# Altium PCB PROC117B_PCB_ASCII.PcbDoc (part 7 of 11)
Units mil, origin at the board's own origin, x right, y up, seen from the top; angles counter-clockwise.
Board outline 2480.32 x 3185.25 mil, 8 copper layers (Top Layer, L2_GND1, L3_SIG1, L4_PWR1, L5_PWR2, L6_SIG2, L7_GND2, Bottom Layer), stack 57.4 mil thick; 456 components, 292 nets, 7831 pads, 2905 vias.
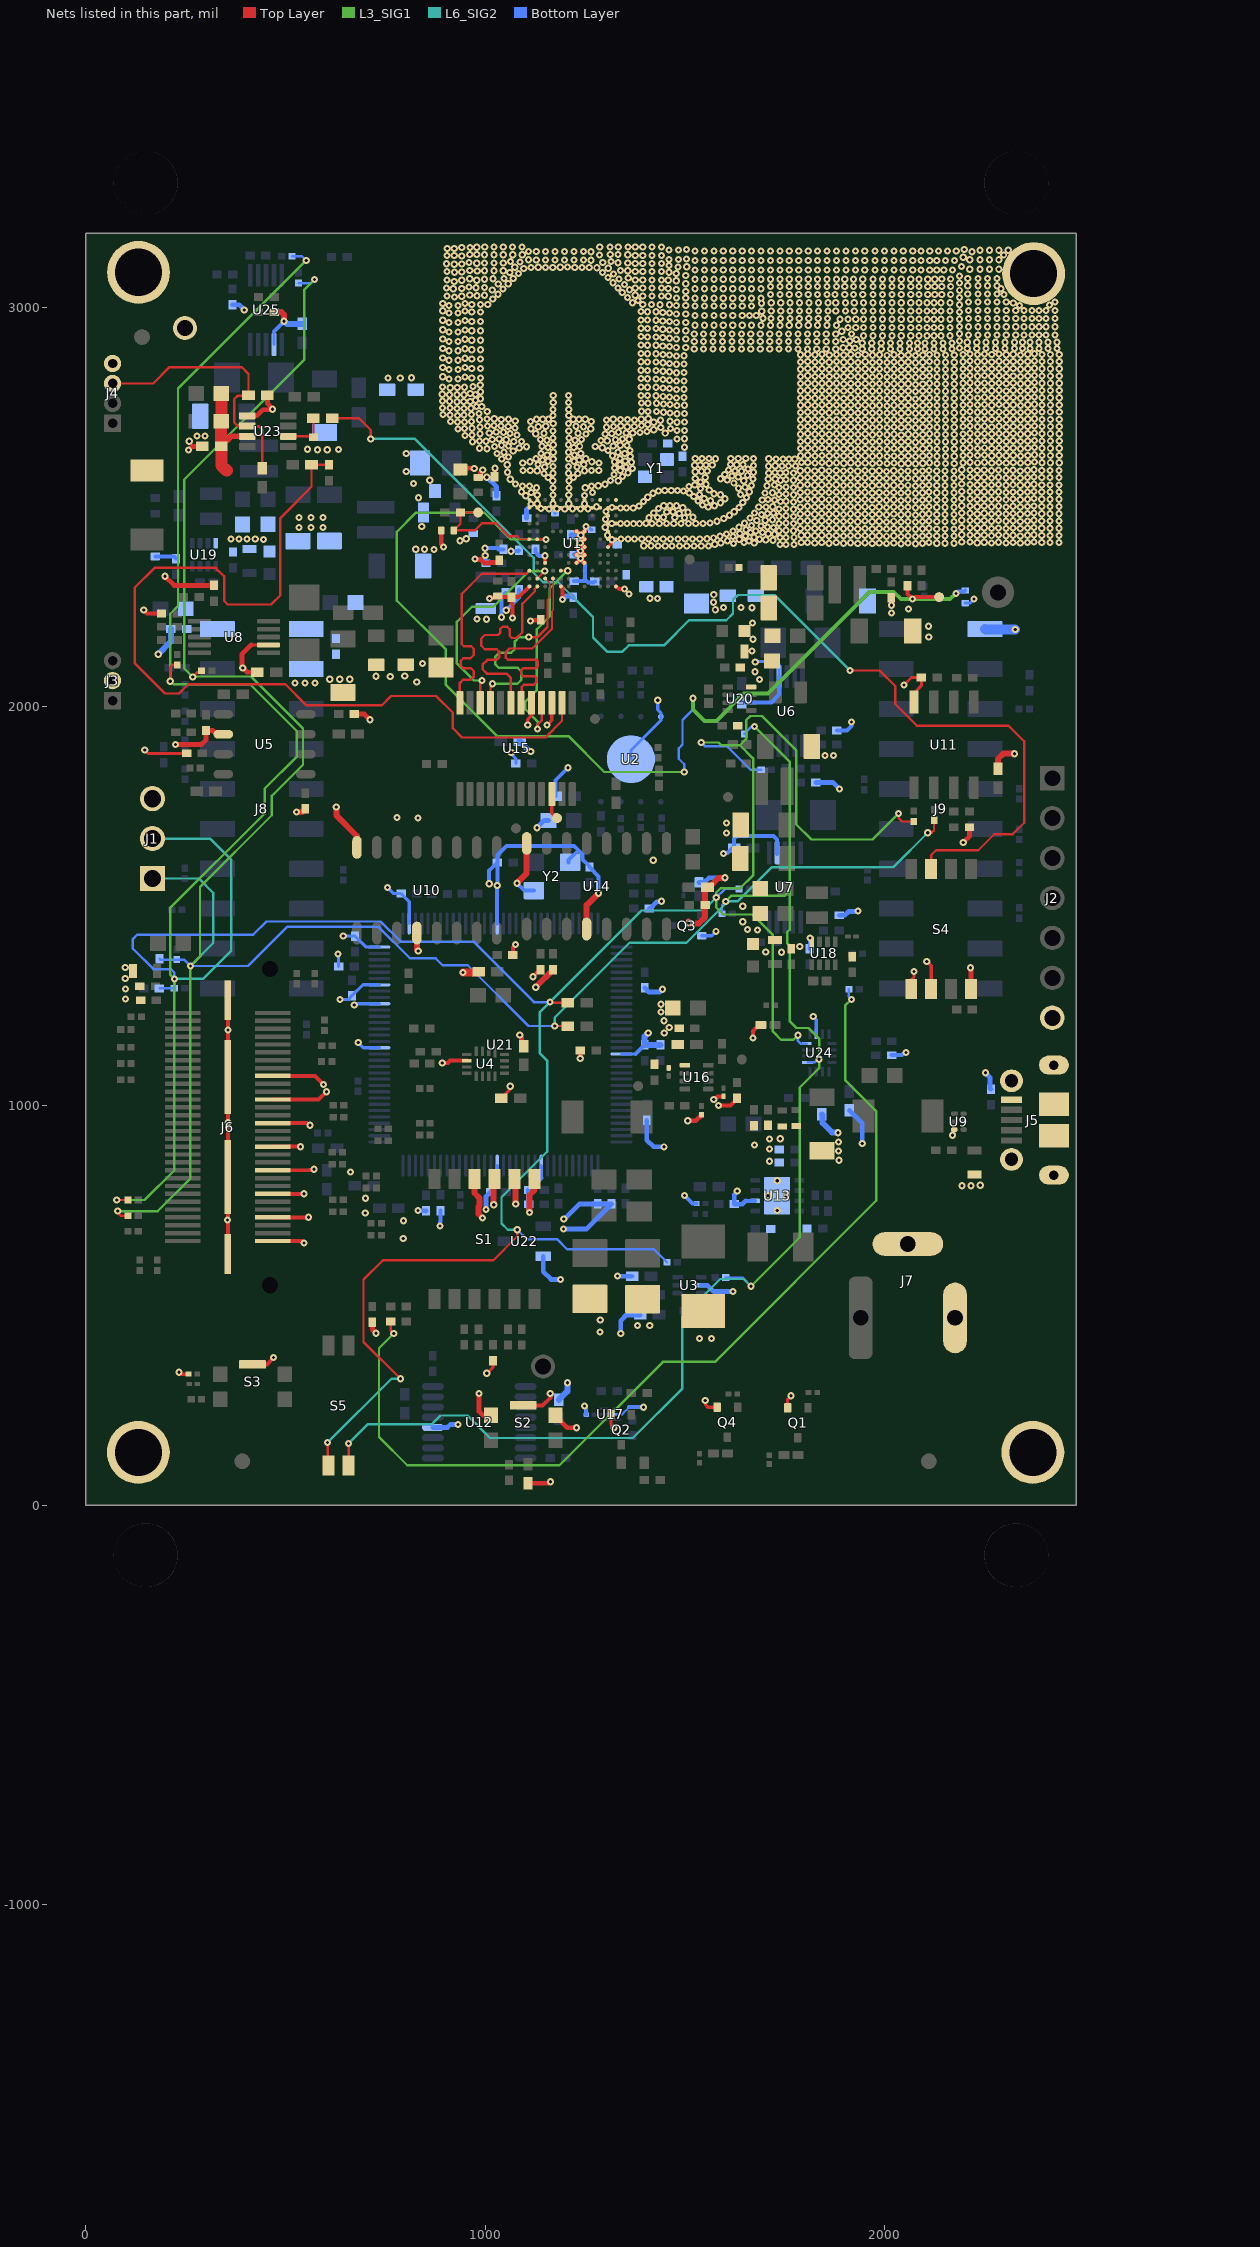
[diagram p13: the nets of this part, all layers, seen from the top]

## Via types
v1: diameter 18, hole 8, Top Layer to Bottom Layer, tented both sides, 2905 vias

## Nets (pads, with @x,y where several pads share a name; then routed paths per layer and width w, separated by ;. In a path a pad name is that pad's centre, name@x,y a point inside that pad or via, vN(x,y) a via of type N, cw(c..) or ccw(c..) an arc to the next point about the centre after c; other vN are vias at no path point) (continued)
GND: (continued)
  other v1: 1536.55,417.61 1566.9,417.41 1287.94,433.2 1412.13,449.56 1381.78,449.77 1288.15,463.55 795.12,668.03 795.33,712.3 355.21,714.33 700.04,731.39 1731.38,737.47 700.51,768.49 1708.74,774.87 1754.02,774.87 2217.09,799.67 2194.53,799.84 2240.14,801.11 1731.38,812.28 663.11,833.85 1711.82,861.19 1886.56,863.55 1885.12,886.6 1712.02,891.54 1674.89,901.72 1885.29,909.16 1712.13,916.92 1739.31,917.56 355.99,958.21 1448.42,1182.03 355.94,1190.15 1461.17,1195.9 1447.75,1213.13 1440.3,1234.53 1440.3,1254.46 99.38,1267.52 99.33,1292.7 98.95,1319.01 98.95,1346.6 2105.95,1361.7 1742.49,1384.61 1702.56,1384.95 1787.95,1399.06 1682.42,1440.52 1657.12,1441.17 1645.39,1461.13 1645.39,1499.52 1420.92,1615.15 1604.29,1683.49 1604.29,1707.83 831.95,1720.71 779.22,1722.34 1851.38,1877.06 1872.61,1876.92 523.71,2058.59 548.71,2058.59 573.71,2058.59 828.91,2060.93 610.98,2068.23 635.98,2068.23 660.98,2068.23 1687.01,2067.9 726.85,2075.64 762.35,2075.35 798.88,2076.3 1675.94,2086.91 393.01,2096.59 843.11,2107.93 1667.97,2138.79 1670.95,2168.51 2111.01,2174.02 2110.57,2200.71 1669.55,2209.4 1003.36,2218.24 979.57,2219.31 2017.74,2233.8 1576.55,2242.32 2060.36,2243.96 1641.05,2247.55 1668.58,2247.22 1596.86,2248.24 1571.87,2261.18 1431.89,2270.66 1412.75,2271.25 1572.34,2280.03 1360.45,2281.33 1348.75,2294.15 1238.93,2370.7 871.91,2392.77 826.51,2393.82 848.52,2393.82 1450.96,2401.65 1397.25,2402.44 1415.39,2402.27 1433.24,2402.02 1468.31,2402.01 1486.55,2402.05 1504.79,2402.09 1523.03,2402.12 1541.27,2402.16 1559.51,2402.2 1738.18,2405.32 1753.63,2405.34 1773.77,2405.46 1574.91,2406.09 2041.42,2407.71 2077.43,2407.46 1622.03,2407.89 1897.36,2408.72 1933.37,2408.47 1969.39,2408.22 2005.4,2407.97 2131.2,2408.62 2151.98,2408.62 2174.14,2408.62 1590.21,2409.74 1674.06,2409.36 1825.33,2409.23 1861.35,2408.97 1987.14,2409.63 2023.15,2409.37 2059.17,2409.12 2095.18,2408.87 2268.23,2409.7 2304.24,2409.45 2340.25,2409.2 1843.08,2410.63 1879.1,2410.38 1915.11,2410.13 1951.12,2409.88 2111.93,2410.28 2232.21,2409.96 2358,2410.61 2394.02,2410.35 2414.8,2410.35 2436.97,2410.35 1648.2,2410.8 1791.62,2410.87 1807.07,2410.89 2213.95,2411.62 2249.96,2411.36 2285.98,2411.11 2321.99,2410.86 2193.82,2412.17 2374.76,2412.01 1660.77,2414.39 937.19,2414.96 1606.94,2415.04 1721.01,2416.35 1702.74,2417.63 445.22,2418.18 1636.35,2418.7 1687.02,2418.59 363.39,2419.56 383.33,2419.21 403.96,2419.21 424.59,2419.56 1339.99,2419.49 1357.98,2419.17 1374.39,2419.42 1392.26,2419.3 1409.89,2419.45 1428.23,2419.33 1446.14,2419.07 1464.32,2419.53 1482.91,2419.31 1500.99,2419.52 1519.4,2419.31 1537.68,2419.3 952.63,2420.11 1555.84,2419.96 1572.09,2422.29 1673.23,2423.72 1738.18,2423.4 1753.63,2423.42 1773.77,2423.54 2077.43,2425.54 1588.13,2426.17 1621.12,2425.86 1651.79,2426.6 1933.37,2426.55 1969.39,2426.3 2005.4,2426.05 2041.42,2425.79 2131.2,2426.7 2151.98,2426.7 2174.14,2426.7 1825.33,2427.31 1861.35,2427.05 1897.36,2426.8 1987.14,2427.71 2023.15,2427.45 2059.17,2427.2 2095.18,2426.95 2304.24,2427.53 2340.25,2427.28 1306.27,2428.57 1843.08,2428.71 1879.1,2428.46 1915.11,2428.21 1951.12,2427.96 2111.93,2428.36 2232.21,2428.04 2268.23,2427.78 2358,2428.69 2394.02,2428.43 2414.8,2428.43 2436.97,2428.43 1791.62,2428.95 1807.07,2428.97 2213.95,2429.7 2249.96,2429.44 2285.98,2429.19 2321.99,2428.94 2193.82,2430.25 2374.76,2430.09 1724.86,2431.1 1604.15,2431.81 1708.83,2432.7 1637.69,2433.53 1664.6,2435.68 1694.42,2435.61 1621.12,2439.44 1677.72,2439.12 1735.88,2440.09 1771.9,2439.84 1753.63,2441.5 1653.07,2442.8 2077.43,2443.62 1933.37,2444.63 1969.39,2444.38 2005.4,2444.13 2041.42,2443.87 1789.32,2445.64 1825.33,2445.39 1861.35,2445.13 1897.36,2444.88 2023.15,2445.53 2059.17,2445.28 2095.18,2445.03 2131.2,2444.78 2151.98,2444.78 2174.14,2444.78 2304.24,2445.61 2340.25,2445.36 1879.1,2446.54 1915.11,2446.29 1951.12,2446.04 1987.14,2445.79 2111.93,2446.44 2232.21,2446.11 2268.23,2445.86 2394.02,2446.51 2414.8,2446.51 2436.97,2446.51 1807.07,2447.05 1843.08,2446.79 2249.96,2447.52 2285.98,2447.27 2321.99,2447.02 2358,2446.77 534.07,2448.57 564.07,2448.57 594.07,2448.57 1636.1,2448.75 1721.99,2448.55 2193.82,2448.33 2213.95,2447.78 2374.76,2448.17 1300.69,2448.9 1707.02,2449.63 841.48,2450.44 1691.16,2451.79 1666.75,2453.12 1317.26,2458.22 1338.97,2458.23 1354.94,2458.23 1371.71,2457.83 1386.88,2457.83 1402.58,2458.7 1417.88,2458.06 1436.12,2458.1 1454.36,2458.13 1472.6,2458.17 1490.84,2458.21 1509.08,2458.24 1527.32,2458.28 1545.56,2458.32 1735.88,2458.17 1771.9,2457.92 1563.14,2459.64 1649.78,2459.07 1753.63,2459.58 2077.43,2461.7 1933.37,2462.71 1969.39,2462.46 2005.4,2462.21 2041.42,2461.95 1789.32,2463.72 1825.33,2463.47 1861.35,2463.21 1897.36,2462.96 2023.15,2463.61 2059.17,2463.36 2095.18,2463.11 2131.2,2462.86 2151.98,2462.86 2174.14,2462.86 2304.24,2463.69 2340.25,2463.44 1580.37,2464.01 1879.1,2464.62 1915.11,2464.37 1951.12,2464.12 1987.14,2463.87 2111.93,2464.52 2232.21,2464.19 2268.23,2463.94 2394.02,2464.59 2414.8,2464.59 2436.97,2464.59 1807.07,2465.13 1843.08,2464.87 2249.96,2465.6 2285.98,2465.35 2321.99,2465.1 2358,2464.85 1680.32,2466.03 1701.43,2466.4 2193.82,2466.41 2213.95,2465.85 2374.76,2466.25 1719.64,2467.66 1301.25,2468.94 1597.41,2470.41 1410.42,2472.74 1499.03,2472.56 1663.36,2471.98 534.07,2473.57 564.07,2473.57 594.07,2473.57 1431.41,2473.4 1474.95,2472.87 1446.85,2473.95 1520.48,2474.06 1735.88,2476.25 1771.9,2476 1753.63,2477.66 1611.76,2478.82 1691.91,2480.51 1969.39,2480.54 2005.4,2480.29 2041.42,2480.03 2077.43,2479.78 1825.33,2481.55 1861.35,2481.29 1897.36,2481.04 1933.37,2480.79 2023.15,2481.69 2059.17,2481.44 2095.18,2481.19 2131.2,2480.94 2151.98,2480.94 2174.14,2480.94 2340.25,2481.52 1789.32,2481.8 1879.1,2482.7 1915.11,2482.45 1951.12,2482.2 1987.14,2481.95 2111.93,2482.6 2232.21,2482.27 2268.23,2482.02 2304.24,2481.77 2394.02,2482.67 2414.8,2482.67 2436.97,2482.67 1486.25,2483.6 1707.03,2483.55 1807.07,2483.21 1843.08,2482.95 2249.96,2483.68 2285.98,2483.43 2321.99,2483.18 2358,2482.93 1422.35,2484.47 1674.3,2484.71 1722.5,2484.29 2193.82,2484.49 2213.95,2483.93 2374.76,2484.33 1507.71,2486.3 1454.96,2487.25 1470.87,2487.43 1624.03,2487.59 1302.46,2488.02 1160.05,2494.71 1199.42,2494.71 1238.79,2494.71 1735.88,2494.33 1771.9,2494.08 1218.61,2495.02 1257.98,2495.02 1753.63,2495.74 1140.28,2495.8 1433.93,2496.09 1339.22,2496.98 1354.1,2497.07 1370.76,2497.13 1317.67,2497.96 1495.08,2497.88 1635.52,2498.09 1969.39,2498.62 2005.4,2498.37 2041.42,2498.11 2077.43,2497.86 1558.63,2499.73 1685.26,2499.44 1703.68,2499.62 1825.33,2499.63 1861.35,2499.37 1897.36,2499.12 1933.37,2498.87 2059.17,2499.52 2095.18,2499.27 2131.2,2499.02 2151.98,2499.02 2174.14,2499.02 2340.25,2499.6 1278.65,2500.2 1720.09,2500.26 1789.32,2499.88 1915.11,2500.53 1951.12,2500.28 1987.14,2500.03 2023.15,2499.77 2111.93,2500.68 2232.21,2500.35 2268.23,2500.1 2304.24,2499.85 2394.02,2500.75 2414.8,2500.75 2436.97,2500.75 1807.07,2501.29 1843.08,2501.03 1879.1,2500.78 2249.96,2501.76 2285.98,2501.51 2321.99,2501.26 2358,2501.01 1385.72,2502.41 1447.31,2502.45 1462.85,2502.6 1479.37,2502.46 1574.55,2502.66 2193.82,2502.57 2213.95,2502.01 2374.76,2502.41 1544.26,2504.2 1130.76,2507.47 1170.13,2507.47 1209.5,2507.47 1248.87,2507.47 1589.43,2510.02 1645.2,2510.9 1771.9,2512.16 1396.81,2513.32 1739.41,2513.59 1753.63,2513.82 1533.25,2514.93 1564.08,2515.06 1969.39,2516.7 2005.4,2516.45 2041.42,2516.19 2077.43,2515.94 1694.17,2516.82 1724.74,2516.77 1825.33,2517.71 1861.35,2517.45 1897.36,2517.2 1933.37,2516.95 2059.17,2517.6 2095.18,2517.35 2131.2,2517.1 2151.98,2517.1 2174.14,2517.1 2340.25,2517.68 1708.6,2518.23 1789.32,2517.96 1915.11,2518.61 1951.12,2518.36 1987.14,2518.11 2023.15,2517.85 2111.93,2518.76 2232.21,2518.43 2268.23,2518.18 2304.24,2517.93 1807.07,2519.37 1843.08,2519.11 1879.1,2518.86 2285.98,2519.59 2321.99,2519.34 2358,2519.09 2394.02,2518.83 2414.8,2518.83 2436.97,2518.83 1548.71,2520.55 1600.43,2520.22 2193.82,2520.65 2213.95,2520.09 2249.96,2519.84 2374.76,2520.49 833.16,2522.75 1654.52,2523.26 1407.45,2524 1522.58,2525.72 1101.57,2527.54 1248.8,2528.15 1130.65,2529.57 1170.02,2529.57 1209.39,2529.57 1589.48,2530.14 1639.75,2530.55 1735.88,2530.49 1771.9,2530.24 1536.52,2531.2 1573.38,2532.68 1753.63,2531.9 1420.14,2533.8 1511.34,2534.55 1701.19,2534.53 2005.4,2534.53 2041.42,2534.27 2077.43,2534.02 1719.49,2535.05 1861.35,2535.53 1897.36,2535.28 1933.37,2535.03 1969.39,2534.78 2059.17,2535.68 2095.18,2535.43 2131.2,2535.18 2151.98,2535.18 2174.14,2535.18 2340.25,2535.76 1115.75,2535.95 1269.15,2535.77 1789.32,2536.04 1825.33,2535.79 1915.11,2536.69 1951.12,2536.44 1987.14,2536.19 2023.15,2535.93 2232.21,2536.51 2268.23,2536.26 2304.24,2536.01 1661.62,2537.53 1807.07,2537.45 1843.08,2537.19 1879.1,2536.94 2111.93,2536.84 2285.98,2537.67 2321.99,2537.42 2358,2537.17 2394.02,2536.91 2414.8,2536.91 2436.97,2536.91 1091.17,2537.87 2193.82,2538.73 2213.95,2538.17 2249.96,2537.92 2374.76,2538.57 1434.32,2539.36 1497.13,2539.85 1449.61,2540.82 1465.99,2541.18 1481.75,2540.87 1561.23,2541.78 1539.71,2545.58 1634.46,2546.4 1169.77,2547.38 1209.71,2547.38 1128.93,2547.89 1250.55,2547.89 1735.88,2548.57 1771.9,2548.32 1650.73,2549.24 1753.63,2549.98 1510.43,2550.81 1093.63,2552.34 1111.45,2552.01 1266.42,2552.46 1283.49,2552.54 2005.4,2552.61 2041.42,2552.35 2077.43,2552.1 1666.95,2553.52 1706.18,2552.95 1861.35,2553.61 1897.36,2553.36 1933.37,2553.11 1969.39,2552.86 2059.17,2553.76 2095.18,2553.51 2131.2,2553.26 2151.98,2553.26 2174.14,2553.26 1525.07,2554.7 1724.51,2554.68 1789.32,2554.12 1825.33,2553.87 1951.12,2554.52 1987.14,2554.27 2023.15,2554.01 2232.21,2554.59 2268.23,2554.34 2304.24,2554.09 2340.25,2553.84 1807.07,2555.53 1843.08,2555.27 1879.1,2555.02 1915.11,2554.77 2111.93,2554.92 2285.98,2555.75 2321.99,2555.5 2358,2555.25 2394.02,2554.99 2414.8,2554.99 2436.97,2554.99 1300.15,2556.33 1552.86,2556.33 2213.95,2556.25 2249.96,2556 2374.76,2556.65 1076.15,2557.45 2193.82,2556.81 820.83,2558.75 1622.87,2559.67 1539.16,2561.93 1169.4,2565.31 1210.08,2565.31 1333.54,2565.25 1647.66,2565.08 861.31,2566.34 1313.95,2565.96 1739.52,2566.33 1771.9,2566.4 1606.16,2567.36 1753.63,2568.06 1062.96,2569 1670.55,2569.7 1709.21,2569.56 1589.56,2570.08 1726.66,2569.77 2005.4,2570.68 2041.42,2570.43 2077.43,2570.18 1526.43,2571.08 1861.35,2571.69 1897.36,2571.44 1933.37,2571.19 1969.39,2570.94 2095.18,2571.59 2131.2,2571.34 2151.98,2571.34 2174.14,2571.34 1789.32,2572.2 1825.33,2571.95 1951.12,2572.6 1987.14,2572.34 2023.15,2572.09 2059.17,2571.84 2232.21,2572.67 2268.23,2572.42 2304.24,2572.17 2340.25,2571.92 1158.09,2573.2 1221.38,2573.2 1551.27,2573.14 1807.07,2573.61 1843.08,2573.35 1879.1,2573.1 1915.11,2572.85 2111.93,2573 2321.99,2573.58 2358,2573.33 2394.02,2573.07 2414.8,2573.07 2436.97,2573.07 1633.68,2574.44 2213.95,2574.33 2249.96,2574.08 2285.98,2573.83 2374.76,2574.73 2193.82,2574.89 1343.88,2576.03 1618.03,2577.04 1657.08,2578.8 1322.5,2581.15 1599.97,2581.08 1147.68,2583.48 1231.8,2583.48 1170.32,2583.98 1209.15,2583.98 1710.29,2584.42 1771.9,2584.48 1357.87,2585.5 1739.17,2584.79 1055.75,2586.51 1671.83,2586.68 1726.23,2585.93 1753.63,2586.14 1526.16,2587.61 2041.42,2588.51 2077.43,2588.26 802.65,2588.79 1541.61,2589.25 1556.4,2589.69 1625.95,2589.32 1642.36,2589 1897.36,2589.52 1933.37,2589.27 1969.39,2589.02 2005.4,2588.76 2095.18,2589.67 2131.2,2589.42 2151.98,2589.42 2174.14,2589.42 1113.16,2590.61 1130.78,2590.24 1248.69,2590.24 1266.32,2590.61 1789.32,2590.28 1825.33,2590.03 1861.35,2589.77 1951.12,2590.68 1987.14,2590.42 2023.15,2590.17 2059.17,2589.92 2232.21,2590.75 2268.23,2590.5 2304.24,2590.25 2340.25,2590 1094.85,2591.17 1284.63,2591.17 1338.54,2590.89 1807.07,2591.69 1843.08,2591.43 1879.1,2591.18 1915.11,2590.93 2111.93,2591.08 2321.99,2591.66 2358,2591.41 2394.02,2591.15 2414.8,2591.15 2436.97,2591.15 1609.37,2592.4 2213.95,2592.41 2249.96,2592.16 2285.98,2591.91 2193.82,2592.97 2374.76,2592.81 1658.09,2594.41 1369.23,2596.28 1324.09,2597.38 1149.36,2599.8 1230.11,2599.8 1352.59,2599.85 1170.3,2601.28 1209.17,2601.28 1710,2601.7 1726.66,2602.73 1743.68,2602.3 1759.62,2602.09 1777.5,2602.09 1671.91,2603.17 1524.81,2604 1538.84,2604.42 1055.46,2605.22 1553.35,2604.91 1568.64,2604.79 1630.21,2605.27 1645.93,2605.64 1132.34,2605.94 1247.14,2605.94 1337.57,2605.91 1614.25,2606.17 2078.1,2607.61 1934.04,2608.62 1970.05,2608.37 2006.07,2608.12 2042.08,2607.87 1826,2609.38 1862.01,2609.13 1898.03,2608.87 2023.82,2609.53 2059.83,2609.27 2095.85,2609.02 2131.86,2608.77 2152.64,2608.77 2174.81,2608.77 2304.91,2609.6 2340.92,2609.35 1094.42,2609.91 1285.06,2609.91 1879.76,2610.53 1915.78,2610.28 1951.79,2610.03 1987.8,2609.78 2112.6,2610.43 2196.86,2610.36 2232.88,2610.11 2268.89,2609.85 2358.67,2610.76 2394.68,2610.51 2415.47,2610.51 2437.63,2610.51 1366.64,2611.72 1792.28,2611.02 1807.73,2611.04 1843.75,2610.79 2250.63,2611.51 2286.64,2611.26 2322.66,2611.01 2214.61,2611.77 2375.42,2612.17 1112.2,2612.9 1267.27,2612.9 1323.98,2612.76 1157.26,2614.02 1222.21,2614.02 1351.13,2614.99 1143.57,2617 1235.9,2617 1041.62,2619.44 1170.57,2619.45 1208.9,2619.45 1127.55,2620.36 1251.93,2620.36 1526.01,2620.73 1543.38,2620.73 1560.31,2620.65 1576.66,2620.51 1615.07,2620.65 1633.97,2620.65 1652.87,2620.65 1671.77,2620.65 1710.21,2620.23 1728.72,2620.09 1745.61,2619.91 1760.7,2620.09 1775.25,2620.09 1338.05,2621.17 1058.19,2624.99 2078.1,2625.69 1363.35,2625.99 1934.04,2626.7 1970.05,2626.45 2006.07,2626.2 2042.08,2625.95 1319.37,2627.72 1789.98,2627.71 1826,2627.46 1862.01,2627.21 1898.03,2626.95 2023.82,2627.61 2059.83,2627.35 2095.85,2627.1 2131.86,2626.85 2152.64,2626.85 2174.81,2626.85 2304.91,2627.68 2340.92,2627.43 1879.76,2628.61 1915.78,2628.36 1951.79,2628.11 1987.8,2627.86 2112.6,2628.51 2196.86,2628.44 2232.88,2628.19 2268.89,2627.93 2394.68,2628.59 2415.47,2628.59 2437.63,2628.59 1807.73,2629.12 1843.75,2628.87 2250.63,2629.59 2286.64,2629.34 2322.66,2629.09 2358.67,2628.84 1155.4,2630.09 1224.08,2630.09 2214.61,2629.85 2375.42,2630.25 802.36,2633.25 1029.9,2633.18 1349.57,2633.18 1139.77,2633.83 1239.71,2633.83 1170.44,2636.68 1209.04,2636.68 1047.07,2636.81 1332.41,2636.81 1070.3,2639.53 1362.72,2640.71 1307.81,2640.86 604.68,2642.69 580.47,2643.03 632.98,2643.37 554.87,2643.94 1970.05,2644.53 2006.07,2644.28 2042.08,2644.03 2078.1,2643.77 1004.98,2645.52 1826,2645.54 1862.01,2645.29 1898.03,2645.03 1934.04,2644.78 2023.82,2645.69 2059.83,2645.43 2095.85,2645.18 2131.86,2644.93 2152.64,2644.93 2174.81,2644.93 2304.91,2645.76 2340.92,2645.51 985.61,2646.73 1789.98,2645.79 1879.76,2646.69 1915.78,2646.44 1951.79,2646.19 1987.8,2645.94 2112.6,2646.59 2196.86,2646.52 2232.88,2646.27 2268.89,2646.01 2394.68,2646.67 2415.47,2646.67 2437.63,2646.67 1085.55,2647.65 1807.73,2647.2 1843.75,2646.95 2250.63,2647.67 2286.64,2647.42 2322.66,2647.17 2358.67,2646.92 1157.67,2648.22 1221.8,2648.22 1293.13,2647.98 2214.61,2647.93 2375.42,2648.33 1499.21,2649.39 1103.36,2650.5 1023.84,2651.15 1142.73,2651.71 1236.75,2651.71 1275.58,2650.95 1058.78,2651.96 1320.69,2651.96 1355.09,2653.47 1041.21,2653.98 1338.26,2653.98 1170.53,2655.21 1208.95,2655.21 1970.05,2662.61 2006.07,2662.36 2042.08,2662.1 2078.1,2661.85 968.06,2663.07 1071.91,2663.27 1091.39,2663.32 1826,2663.62 1862.01,2663.37 1898.03,2663.11 1934.04,2662.86 2059.83,2663.51 2095.85,2663.26 2131.86,2663.01 2152.64,2663.01 2174.81,2663.01 2340.92,2663.59 259.04,2664.27 1001.95,2664.28 1789.98,2663.87 1915.78,2664.52 1951.79,2664.27 1987.8,2664.02 2023.82,2663.76 2112.6,2664.67 2196.86,2664.6 2232.88,2664.35 2268.89,2664.09 2304.91,2663.84 2394.68,2664.75 2415.47,2664.75 2437.63,2664.75 986.22,2664.89 1290.23,2665.72 1305.78,2665.43 1807.73,2665.28 1843.75,2665.03 1879.76,2664.77 2250.63,2665.75 2286.64,2665.5 2322.66,2665.25 2358.67,2665 2214.61,2666.01 2375.42,2666.41 1052.92,2667.71 1154.69,2666.86 1224.78,2666.86 1326.55,2667.71 1017.99,2668.32 1138.46,2668.92 1241.01,2668.92 1360.78,2669.23 1035.35,2670.14 1344.12,2670.14 1480.49,2669.85 1499.21,2670.39 1169.75,2672.52 1209.72,2672.52 278.43,2677.05 298.16,2677.28 949.3,2678.8 1079.69,2679.65 967.46,2680.01 1970.05,2680.69 2006.07,2680.44 2042.08,2680.18 2078.1,2679.93 1826,2681.7 1862.01,2681.45 1898.03,2681.19 1934.04,2680.94 2059.83,2681.59 2095.85,2681.34 2131.86,2681.09 2152.64,2681.09 2174.81,2681.09 2340.92,2681.67 1252.29,2682.54 1300.61,2681.98 1789.98,2681.95 1915.78,2682.6 1951.79,2682.35 1987.8,2682.1 2023.82,2681.84 2112.6,2682.75 2196.86,2682.68 2232.88,2682.43 2268.89,2682.17 2304.91,2681.92 987.43,2683.04 1062.22,2683.47 1126.97,2682.87 1317.26,2683.47 1807.73,2683.36 1843.75,2683.11 1879.76,2682.85 2286.64,2683.58 2322.66,2683.33 2358.67,2683.08 2394.68,2682.83 2415.47,2682.83 2437.63,2682.83 1147.21,2684.16 1232.26,2684.16 1353.28,2684.73 1369.82,2684.73 1451.21,2684.47 2214.61,2684.09 2250.63,2683.83 2375.42,2684.49 1010.51,2684.88 1045.65,2686.49 1333.82,2686.49 1388.15,2686.03 1027.68,2687.3 1405.15,2688.27 1170.22,2690.11 1209.26,2690.11 1480.49,2690.85 1499.21,2691.39 1422.37,2693.19 931.75,2695.14 948.7,2695.75 1114.86,2695.37 1264.61,2695.37 1463.96,2696.09 966.85,2696.96 1075.07,2697.43 1439.81,2698.55 2006.07,2698.52 2042.08,2698.26 2078.1,2698.01 1304.14,2699.46 1862.01,2699.53 1898.03,2699.27 1934.04,2699.02 1970.05,2698.77 2059.83,2699.67 2095.85,2699.42 2131.86,2699.17 2152.64,2699.17 2174.81,2699.17 2340.92,2699.75 986.82,2699.98 1132.86,2700.67 1246.61,2700.67 1356.13,2700.49 1789.98,2700.03 1826,2699.78 1915.78,2700.68 1951.79,2700.43 1987.8,2700.18 2023.82,2699.92 2196.86,2700.76 2232.88,2700.51 2268.89,2700.25 2304.91,2700 1057.77,2700.83 1151.96,2701.64 1227.51,2701.64 1321.7,2700.83 1373.69,2701.27 1807.73,2701.44 1843.75,2701.19 1879.76,2700.93 2112.6,2700.83 2286.64,2701.66 2322.66,2701.41 2358.67,2701.16 2394.68,2700.91 2415.47,2700.91 2437.63,2700.91 1005.67,2702.65 1040,2702.25 1339.47,2702.25 2214.61,2702.17 2250.63,2701.91 2375.42,2702.57 1022.43,2703.66 1391.52,2703.85 1407.28,2706.44 1170.57,2708.28 1208.9,2708.28 1422.52,2711.6 931.15,2712.09 948.09,2712.69 1480.49,2711.85 1499.21,2712.39 912.99,2713.3 1113.57,2713.7 1265.85,2713.35 966.25,2713.9 1463.2,2714.11 1075.56,2715.25 2006.07,2716.6 2042.08,2716.34 2078.1,2716.09 1303.93,2717.15 1373.97,2717.46 1439.21,2716.88 1862.01,2717.61 1898.03,2717.35 1934.04,2717.1 1970.05,2716.85 2059.83,2717.75 2095.85,2717.5 2131.86,2717.25 2152.64,2717.25 2174.81,2717.25 985.61,2718.14 1356.69,2718.37 1789.98,2718.11 1826,2717.86 1915.78,2718.76 1951.79,2718.51 1987.8,2718.26 2023.82,2718 2232.88,2718.59 2268.89,2718.33 2304.91,2718.08 2340.92,2717.83 1040.61,2719.01 1058.71,2719.12 1128.54,2719.33 1144.19,2719.33 1158.76,2719.12 1220.72,2719.12 1235.28,2719.33 1250.93,2719.33 1320.76,2719.12 1338.87,2719.01 1390.81,2719.28 1807.73,2719.52 1843.75,2719.27 1879.76,2719.01 2112.6,2718.91 2196.86,2718.84 2286.64,2719.74 2322.66,2719.49 2358.67,2719.24 2394.68,2718.99 2415.47,2718.99 2437.63,2718.99 1005.06,2720.02 1023.03,2720.42 1408.55,2720.65 2214.61,2720.25 2250.63,2719.99 2375.42,2720.65 1170.19,2728.4 1209.28,2728.4 930.54,2729.03 947.49,2729.64 912.39,2730.24 894.23,2730.85 965.64,2730.85 1480.49,2732.85 1499.21,2733.39 985.01,2733.87 2006.07,2734.68 2042.08,2734.42 2078.1,2734.17 1463.2,2735.11 1862.01,2735.69 1898.03,2735.43 1934.04,2735.18 1970.05,2734.93 2095.85,2735.58 2131.86,2735.33 2152.64,2735.33 2174.81,2735.33 1446.41,2736.64 1789.98,2736.19 1826,2735.94 1951.79,2736.59 1987.8,2736.34 2023.82,2736.08 2059.83,2735.83 2232.88,2736.67 2268.89,2736.41 2304.91,2736.16 2340.92,2735.91 1807.73,2737.6 1843.75,2737.35 1879.76,2737.09 1915.78,2736.84 2112.6,2736.99 2196.86,2736.92 2322.66,2737.57 2358.67,2737.32 2394.68,2737.07 2415.47,2737.07 2437.63,2737.07 1005.26,2738.6 1408.22,2738.47 1429.29,2738.34 2214.61,2738.33 2250.63,2738.07 2286.64,2737.82 2375.42,2738.73 1391.84,2739.13 1170.16,2743.54 1209.31,2743.54 467.72,2744.3 929.94,2745.98 946.88,2746.58 911.78,2747.19 964.31,2746.81 893.63,2747.79 978.07,2751.02 991.66,2751.42 2006.07,2752.76 2042.08,2752.5 2078.1,2752.25 1898.03,2753.51 1934.04,2753.26 1970.05,2753.01 2095.85,2753.66 2131.86,2753.41 2152.64,2753.41 2174.81,2753.41 1480.49,2753.85 1499.21,2754.39 1789.98,2754.27 1826,2754.02 1862.01,2753.76 1951.79,2754.67 1987.8,2754.42 2023.82,2754.16 2059.83,2753.91 2232.88,2754.75 2268.89,2754.49 2304.91,2754.24 2340.92,2753.99 1807.73,2755.68 1843.75,2755.42 1879.76,2755.17 1915.78,2754.92 2112.6,2755.07 2196.86,2755 2322.66,2755.65 2358.67,2755.4 2394.68,2755.15 2415.47,2755.15 2437.63,2755.15 1463.2,2756.11 2214.61,2756.41 2250.63,2756.15 2286.64,2755.9 1446.41,2757.64 2375.42,2756.81 1408.22,2759.47 1429.29,2759.34 1391.84,2760.13 1170.41,2761.07 1209.06,2761.07 929.33,2762.92 946.28,2763.52 962.78,2763.63 893.02,2764.73 911.18,2764.13 975.78,2766.69 2042.08,2770.58 2078.1,2770.33 988.64,2770.79 1898.03,2771.59 1934.04,2771.34 1970.05,2771.09 2006.07,2770.84 2095.85,2771.74 2131.86,2771.49 2152.64,2771.49 2174.81,2771.49 1789.98,2772.35 1826,2772.1 1862.01,2771.84 1951.79,2772.75 1987.8,2772.5 2023.82,2772.24 2059.83,2771.99 2268.89,2772.57 2304.91,2772.32 2340.92,2772.07 1479.25,2772.86 1497.97,2773.4 1807.73,2773.76 1843.75,2773.5 1879.76,2773.25 1915.78,2773 2112.6,2773.15 2196.86,2773.08 2232.88,2772.83 2322.66,2773.73 2358.67,2773.48 2394.68,2773.23 2415.47,2773.23 2437.63,2773.23 2214.61,2774.49 2250.63,2774.23 2286.64,2773.98 1461.96,2775.12 2375.42,2774.89 1445.16,2776.64 1170.41,2778.6 1209.06,2778.6 1406.98,2778.48 1428.04,2778.35 1390.59,2779.14 910.57,2780.47 929.33,2780.47 947.49,2780.47 892.42,2781.68 976.16,2781.59 962.78,2783.89 988.64,2788.34 2042.08,2788.66 2078.1,2788.41 1898.03,2789.67 1934.04,2789.42 1970.05,2789.17 2006.07,2788.92 2131.86,2789.57 2152.64,2789.57 2174.81,2789.57 1789.98,2790.43 1826,2790.18 1862.01,2789.92 1987.8,2790.58 2023.82,2790.32 2059.83,2790.07 2095.85,2789.82 2268.89,2790.65 2304.91,2790.4 2340.92,2790.15 1843.75,2791.58 1879.76,2791.33 1915.78,2791.08 1951.79,2790.83 2112.6,2791.23 2196.86,2791.16 2232.88,2790.91 2358.67,2791.56 2394.68,2791.31 2415.47,2791.31 2437.63,2791.31 1807.73,2791.84 2214.61,2792.57 2250.63,2792.31 2286.64,2792.06 2322.66,2791.81 2375.42,2792.97 1479.25,2793.86 1497.97,2794.4 1461.96,2796.12 1445.16,2797.64 912.66,2798.3 893.08,2799.7 930.16,2798.9 948.38,2799.19 1406.98,2799.48 1428.04,2799.35 1390.59,2800.14 969.44,2801.02 988.03,2805.28 2042.08,2806.74 2078.1,2806.49 1898.03,2807.75 1934.04,2807.5 1970.05,2807.25 2006.07,2807 2131.86,2807.65 2152.64,2807.65 2174.81,2807.65 1789.98,2808.51 1826,2808.26 1862.01,2808 1987.8,2808.66 2023.82,2808.4 2059.83,2808.15 2095.85,2807.9 2268.89,2808.73 2304.91,2808.48 2340.92,2808.23 1843.75,2809.66 1879.76,2809.41 1915.78,2809.16 1951.79,2808.91 2112.6,2809.31 2196.86,2809.24 2232.88,2808.99 2358.67,2809.64 2394.68,2809.39 2415.47,2809.39 2437.63,2809.39 1807.73,2809.92 2214.61,2810.65 2250.63,2810.39 2286.64,2810.14 2322.66,2809.89 2375.42,2811.05 1479.25,2814.86 1497.97,2815.4 1461.96,2817.12 1445.16,2818.64 909.78,2819.87 931.94,2819.87 1406.98,2820.48 1428.04,2820.35 1390.59,2821.14 966.56,2822.59 988.72,2822.59 756.86,2822.8 787.25,2822.86 815.42,2823.06 2078.1,2824.57 894.07,2825.53 949.36,2825.02 1934.04,2825.58 1970.05,2825.33 2006.07,2825.08 2042.08,2824.82 2131.86,2825.73 2152.64,2825.73 2174.81,2825.73 1789.98,2826.59 1826,2826.34 1862.01,2826.08 1898.03,2825.83 1987.8,2826.74 2023.82,2826.48 2059.83,2826.23 2095.85,2825.98 2304.91,2826.56 2340.92,2826.31 1843.75,2827.74 1879.76,2827.49 1915.78,2827.24 1951.79,2826.99 2112.6,2827.39 2196.86,2827.32 2232.88,2827.07 2268.89,2826.81 2358.67,2827.72 2394.68,2827.47 2415.47,2827.47 2437.63,2827.47 1807.73,2828 2214.61,2828.73 2250.63,2828.47 2286.64,2828.22 2322.66,2827.97 2375.42,2829.12 1479.25,2835.86 1497.97,2836.4 1461.96,2838.12 1445.16,2839.64 1406.98,2841.48 1428.04,2841.35 1390.59,2842.14 2078.1,2842.65 909.78,2843.49 931.94,2843.49 1934.04,2843.66 1970.05,2843.41 2006.07,2843.16 2042.08,2842.9 1789.98,2844.67 1826,2844.42 1862.01,2844.16 1898.03,2843.91 2023.82,2844.56 2059.83,2844.31 2095.85,2844.06 2131.86,2843.81 2152.64,2843.81 2174.81,2843.81 2304.91,2844.64 2340.92,2844.39 1879.76,2845.57 1915.78,2845.32 1951.79,2845.07 1987.8,2844.82 2112.6,2845.47 2196.86,2845.4 2232.88,2845.15 2268.89,2844.89 2394.68,2845.54 2415.47,2845.54 2437.63,2845.54 966.56,2846.21 988.72,2846.21 1807.73,2846.08 1843.75,2845.82 2250.63,2846.55 2286.64,2846.3 2322.66,2846.05 2358.67,2845.8 2214.61,2846.81 2375.42,2847.2 949.36,2848.64 894.07,2849.15 1479.25,2856.86 1497.97,2857.4 1461.96,2859.12 1445.16,2860.64 2078.1,2860.73 1934.04,2861.74 1970.05,2861.49 2006.07,2861.24 2042.08,2860.98 1406.98,2862.48 1428.04,2862.35 1789.98,2862.75 1826,2862.5 1862.01,2862.24 1898.03,2861.99 2023.82,2862.64 2059.83,2862.39 2095.85,2862.14 2131.86,2861.89 2152.64,2861.89 2174.81,2861.89 2304.91,2862.72 2340.92,2862.47 1390.59,2863.14 1879.76,2863.65 1915.78,2863.4 1951.79,2863.15 1987.8,2862.9 2112.6,2863.55 2196.86,2863.48 2232.88,2863.23 2268.89,2862.97 2394.68,2863.62 2415.47,2863.62 2437.63,2863.62 1807.73,2864.16 1843.75,2863.9 2250.63,2864.63 2286.64,2864.38 2322.66,2864.13 2358.67,2863.88 2214.61,2864.89 2375.42,2865.28 909.78,2867.11 931.94,2867.11 966.56,2869.83 988.72,2869.83 949.36,2872.26 894.07,2872.77 1479.25,2877.86 1497.97,2878.4 1970.05,2879.57 2006.07,2879.32 2042.08,2879.06 2078.1,2878.81 1461.96,2880.12 1826,2880.58 1862.01,2880.32 1898.03,2880.07 1934.04,2879.82 2023.82,2880.72 2059.83,2880.47 2095.85,2880.22 2131.86,2879.97 2152.64,2879.97 2174.81,2879.97 2340.92,2880.55 1445.16,2881.64 1789.98,2880.83 1879.76,2881.73 1915.78,2881.48 1951.79,2881.23 1987.8,2880.98 2112.6,2881.63 2196.86,2881.56 2232.88,2881.31 2268.89,2881.05 2304.91,2880.8 2394.68,2881.7 2415.47,2881.7 2437.63,2881.7 1807.73,2882.24 1843.75,2881.98 2250.63,2882.71 2286.64,2882.46 2322.66,2882.21 2358.67,2881.96 1406.98,2883.48 1428.04,2883.35 2214.61,2882.97 2375.42,2883.36 1390.59,2884.14 909.78,2890.73 931.94,2890.73 966.56,2893.45 988.72,2893.45 1523.61,2895.36 1547.23,2895.36 1570.85,2895.36 1594.48,2895.36 1618.1,2895.36 1641.72,2895.36 1665.34,2895.36 1688.96,2895.36 1712.59,2895.36 1736.21,2895.36 1759.83,2895.36 1783.45,2895.36 1807.07,2895.36 1830.7,2895.36 1854.32,2895.36 1877.94,2895.36 1944.58,2894.94 1968.2,2894.94 1991.82,2894.94 2015.44,2894.94 2039.07,2894.94 2062.69,2894.94 2083.08,2894.94 2101.83,2894.94 2124.1,2894.94 2146.88,2894.94 2169.04,2894.94 894.07,2896.39 949.36,2895.88 2207.4,2896.68 2231.02,2896.68 2254.64,2896.68 2278.27,2896.68 2301.89,2896.68 2325.51,2896.68 2345.9,2896.68 2364.66,2896.68 2386.92,2896.68 2409.7,2896.68 2431.87,2896.68 2187.98,2897.45 1896.61,2898.45 1911.75,2898.45 1926.55,2897.77 1478.88,2898.91 1502.5,2898.91 1461.6,2901.16 1444.8,2902.69 1406.61,2904.53 1427.68,2904.4 1390.23,2905.19 1944.58,2910.56 1968.2,2910.56 1991.82,2910.56 2015.44,2910.56 2039.07,2910.56 2062.69,2910.56 2083.08,2910.56 2101.83,2910.56 2124.1,2910.56 2146.83,2910.56 2169,2910.56 2207.4,2912.3 2231.02,2912.3 2254.64,2912.3 2278.27,2912.3 2301.89,2912.3 2325.51,2912.3 2345.9,2912.3 2364.66,2912.3 2386.92,2912.3 2409.66,2912.3 2431.82,2912.3 909.78,2914.35 931.94,2914.35 1523.61,2913.9 1547.23,2913.9 1570.85,2913.9 1594.48,2913.9 1618.1,2913.9 1641.72,2913.9 1665.34,2913.9 1688.96,2913.9 1712.59,2913.9 1736.21,2913.9 1759.83,2913.9 1783.45,2913.9 1807.07,2913.9 1830.7,2913.9 1854.32,2913.9 1877.94,2913.9 1913.09,2915.61 2187.98,2915.53 966.56,2917.08 988.72,2917.08 1896.61,2918.63 949.36,2919.5 1929.21,2919.36 894.07,2920.01 1478.88,2919.91 1502.5,2919.91 1461.6,2922.16 1444.8,2923.69 1406.61,2925.53 1427.68,2925.4 1390.23,2926.19 1947.81,2928.36 1971.43,2928.36 1995.05,2928.36 2018.67,2928.36 2042.29,2928.36 2065.92,2928.36 2086.31,2928.36 2106.7,2928.36 2124.1,2928.36 2141.88,2928.36 2164.04,2928.36 2210.63,2930.09 2234.25,2930.09 2257.87,2930.09 2281.49,2930.09 2305.12,2930.09 2328.74,2930.09 2349.13,2930.09 2369.53,2930.09 2386.92,2930.09 2404.7,2930.09 2426.87,2930.09 1523.61,2932.98 1547.23,2932.98 1570.85,2932.98 1594.48,2932.98 1618.1,2932.98 1641.72,2932.98 1665.34,2932.98 1688.96,2932.98 1712.59,2932.98 1736.21,2932.98 1759.83,2932.98 1783.45,2932.98 1807.07,2932.98 1830.7,2932.98 1854.32,2932.98 1877.94,2932.98 1917.7,2933.12 2187.98,2933.61 909.78,2937.98 931.94,2937.98 1892.91,2939.49 966.56,2940.7 988.72,2940.7 1478.88,2940.91 1502.5,2940.91 894.07,2943.64 949.36,2943.13 1461.6,2943.16 1444.8,2944.69 1406.61,2946.53 1427.68,2946.4 1390.23,2947.19 1908.56,2948.98 1928.18,2948.98 1947.81,2948.98 1971.43,2948.98 1995.05,2948.98 2018.67,2948.98 2042.29,2948.98 2065.92,2948.98 2086.31,2948.98 2106.7,2948.98 2124.1,2948.98 2141.88,2948.98 2164.04,2948.98 2210.63,2950.72 2234.25,2950.72 2257.87,2950.72 2281.49,2950.72 2305.12,2950.72 2328.74,2950.72 2349.13,2950.72 2369.53,2950.72 2386.92,2950.72 2404.7,2950.72 2426.87,2950.72 2187.98,2951.69 1525.61,2954.6 1549.23,2954.6 1572.85,2954.6 1596.48,2954.6 1620.1,2954.6 1643.72,2954.6 1667.34,2954.6 1690.96,2954.6 1714.59,2954.6 1738.21,2954.6 1761.83,2954.6 1785.45,2954.6 1809.07,2954.6 1832.7,2954.6 1856.32,2954.6 1879.94,2954.6 909.78,2961.6 931.94,2961.6 1478.88,2961.91 1502.5,2961.91 966.56,2964.32 988.72,2964.32 1461.6,2964.16 1444.8,2965.69 949.36,2966.75 894.07,2967.26 1406.61,2967.53 1427.68,2967.4 1390.23,2968.19 1888.94,2969.6 1908.56,2969.6 1928.18,2969.6 1947.81,2969.6 1971.43,2969.6 1995.05,2969.6 2018.67,2969.6 2042.29,2969.6 2065.92,2969.6 2086.31,2969.6 2106.7,2969.6 2124.1,2969.6 2141.88,2969.6 2164.04,2969.6 2187.98,2969.77 2210.63,2971.34 2234.25,2971.34 2257.87,2971.34 2281.49,2971.34 2305.12,2971.34 2328.74,2971.34 2349.13,2971.34 2369.53,2971.34 2386.92,2971.34 2404.7,2971.34 2426.87,2971.34 1696.2,2971.99 1715.95,2971.86 1739.57,2971.86 1763.19,2971.86 1786.81,2971.86 1810.43,2971.86 1834.06,2971.86 1857.68,2971.86 1525.61,2979.22 1549.23,2979.22 1572.85,2979.22 1596.48,2979.22 1620.1,2979.22 1643.72,2979.22 1662.34,2979.22 1678.96,2979.22 1478.88,2982.91 1502.5,2982.91 909.78,2985.22 931.94,2985.22 1461.6,2985.16 1444.8,2986.69 966.56,2987.94 988.72,2987.94 1406.61,2988.53 1427.68,2988.4 2187.98,2987.85 1390.23,2989.19 949.36,2990.37 1692.96,2989.78 1716.59,2990.22 1740.21,2990.22 1763.83,2990.22 1787.45,2990.22 1811.07,2990.22 1834.7,2990.22 1858.32,2990.22 1877.94,2990.22 1902.56,2990.22 1924.18,2990.22 1947.81,2990.22 1971.43,2990.22 1995.05,2990.22 2018.67,2990.22 2042.29,2990.22 2065.92,2990.22 2086.31,2990.22 2106.7,2990.22 2124.1,2990.22 2141.88,2990.22 2164.04,2990.22 894.07,2990.88 2210.63,2991.96 2234.25,2991.96 2257.87,2991.96 2281.49,2991.96 2305.12,2991.96 2328.74,2991.96 2349.13,2991.96 2369.53,2991.96 2386.92,2991.96 2404.7,2991.96 2426.87,2991.96 1525.61,3002.84 1549.23,3002.84 1572.85,3002.84 1596.48,3002.84 1620.1,3002.84 1643.72,3002.84 1667.34,3002.84 909.78,3003.84 931.94,3003.84 1478.88,3003.91 1502.5,3003.91 2337.92,3004.04 2413.48,3005.1 966.56,3006.56 988.72,3006.56 1416.91,3006.29 1437.97,3006.16 1461.6,3006.16 2187.98,3005.93 1006.42,3006.98 1394.59,3007.02 894.07,3009.5 949.36,3008.99 1692.23,3009.59 2322.69,3010.4 1369.12,3010.98 1716.59,3010.84 1740.21,3010.84 1763.83,3010.84 1787.45,3010.84 1811.07,3010.84 1834.7,3010.84 1858.32,3010.84 1877.94,3010.84 1902.56,3010.84 1924.18,3010.84 1947.81,3010.84 1971.43,3010.84 1995.05,3010.84 2018.67,3010.84 2042.29,3010.84 2065.92,3010.84 2086.31,3010.84 2106.7,3010.84 2124.1,3010.84 2141.88,3010.84 2164.04,3010.84 2210.63,3012.58 2234.25,3012.58 2257.87,3012.58 2281.49,3012.58 2305.12,3012.58 2426.87,3012.58 1382.7,3016.85 1018.98,3020.17 1525.61,3022.47 1549.23,3022.47 1572.85,3022.47 1596.48,3022.47 1620.1,3022.47 1643.72,3022.47 1667.34,3022.47 1690.96,3022.47 1479.1,3022.98 1502.5,3022.91 1356.77,3024.17 2187.98,3024.01 923.05,3025.78 941.49,3027.09 1458.57,3027.41 904.55,3028.09 979.83,3028.5 1394.62,3028.17 1418.24,3028.17 1441.86,3028.17 998.27,3029.81 1375.9,3029.89 961.34,3030.81 1714.59,3031.47 1738.21,3031.47 1761.83,3031.47 1785.45,3031.47 1809.07,3031.47 1832.7,3031.47 1856.32,3031.47 1875.94,3031.47 1900.56,3031.47 1922.18,3031.47 1945.81,3031.47 1971.43,3031.47 1995.05,3031.47 2018.67,3031.47 2042.29,3031.47 2065.92,3031.47 2086.31,3031.47 2108.48,3031.47 2125.87,3031.47 2143.65,3031.47 2165.81,3031.47 2299.22,3031.53 1032.17,3032.52 2208.63,3033.2 2234.25,3033.2 2257.87,3033.2 2281.49,3033.2 1343.58,3036.73 1502.5,3039.22 2187.98,3042.09 1018.01,3043.16 1361.39,3043.72 1478.49,3044.42 1045.15,3045.29 920.16,3046.01 941.49,3046.63 1525.61,3046.09 1549.23,3046.09 1572.85,3046.09 1596.48,3046.09 1620.1,3046.09 1643.72,3046.09 1667.34,3046.09 1690.96,3046.09 2292.15,3046.06 903.1,3047.64 1375.99,3047.72 1394.62,3047.72 1441.86,3047.72 1458.58,3046.96 976.94,3048.73 1332.64,3048.29 1417.85,3048.18 998.27,3049.35 959.88,3050.36 1714.59,3052.09 1738.21,3052.09 1761.83,3052.09 1785.45,3052.09 1809.07,3052.09 1832.7,3052.09 1856.32,3052.09 1879.94,3052.09 1900.56,3052.09 1922.18,3052.09 1945.81,3052.09 1971.43,3052.09 1995.05,3052.09 2018.67,3052.09 2042.29,3052.09 2065.92,3052.09 2086.31,3052.09 2108.48,3052.09 2125.87,3052.09 2143.65,3052.09 2165.81,3052.09 2208.63,3053.83 2234.25,3053.83 2257.87,3053.83 2281.49,3053.83 1349.08,3056.81 1032.77,3058.09 1057.92,3058.48 1502.5,3058.77 2187.98,3060.17 1319.87,3061.27 922.47,3064.51 1478.49,3066.16 941.49,3067.21 979.25,3067.23 1458.57,3067.54 904.55,3068.21 1375.99,3068.29 1394.62,3068.29 1418.24,3068.29 1441.86,3068.29 1525.61,3069.71 1549.23,3069.71 1572.85,3069.71 1596.48,3069.71 1620.1,3069.71 1643.72,3069.71 1667.34,3069.71 1690.96,3069.71 1714.59,3069.71 1738.21,3069.71 1761.83,3069.71 1785.45,3069.71 1809.07,3069.71 1832.7,3069.71 1856.32,3069.71 1879.94,3069.71 1900.56,3069.71 1922.18,3069.71 1945.81,3069.71 1971.43,3069.71 1995.05,3069.71 2018.67,3069.71 2042.29,3069.71 2065.92,3069.71 2086.31,3069.73 2108.48,3069.73 2125.87,3069.74 998.27,3069.93 1335.21,3070.24 2143.65,3070.16 2165.81,3070.16 961.34,3070.94 1019.51,3071.29 1070.48,3071.67 2208.63,3071.45 2234.25,3071.45 2257.87,3071.45 2281.49,3071.45 1046.93,3071.93 1358.25,3072.71 1307.52,3074.45 2187.98,3078.25 1502.5,3079.61 1321.66,3083.2 1083.67,3084.02 1478.49,3084.27 923.63,3087.63 1061.61,3086.88 1294.33,3087.01 1460.61,3087.29 941.49,3088.33 904.55,3089.34 1375.99,3089.42 1394.62,3089.42 1418.24,3089.42 1441.86,3089.42 980.41,3090.35 998.27,3091.05 1021.89,3091.05 1045.51,3091.05 1357.36,3091.13 961.34,3092.06 1338.79,3091.91 1525.61,3093.33 1549.23,3093.33 1572.85,3093.33 1596.48,3093.33 1620.1,3093.33 1643.72,3093.33 1667.34,3093.33 1690.96,3093.33 1714.59,3093.33 1738.21,3093.33 1761.83,3093.33 1785.45,3093.33 1809.07,3093.33 1832.7,3093.33 1856.32,3093.33 1879.94,3093.33 1903.56,3093.33 1927.18,3093.33 1950.81,3093.33 1976.43,3093.33 2000.05,3093.33 2023.67,3093.33 2047.29,3093.33 2070.92,3093.33 2091.31,3093.35 2113.48,3093.35 2130.87,3093.36 2148.65,3093.35 2170.81,3093.35 2213.63,3095.07 2239.25,3095.07 2262.87,3095.07 2286.49,3095.07 1096.65,3096.79 1308.19,3097.51 1279.8,3098.55 1114.88,3099.3 1133.08,3099.74 1151.14,3099.15 1169.35,3099 1224.25,3099.62 1242.46,3099.47 1260.8,3099.34 1074.36,3099.9 1187.98,3099.76 1206.19,3100.21 1483.36,3100.67 1504.85,3101.23 2192.98,3101.44 1460.61,3104.24 922.47,3107.28 941.49,3107.88 903.1,3108.88 1375.99,3108.96 1394.62,3108.96 1417.85,3109.43 1441.86,3108.96 979.25,3110 998.27,3110.6 1021.89,3110.6 1045.51,3110.6 1357.36,3110.68 959.88,3111.6 1294.68,3111.6 1332.95,3111.28 1087.6,3112.96 1063.38,3113.95 1315.04,3114.05 1265.02,3117.55 1525.61,3116.95 1549.23,3116.95 1572.85,3116.95 1596.48,3116.95 1620.1,3116.95 1643.72,3116.95 1667.34,3116.95 1690.96,3116.95 1714.59,3116.95 1738.21,3116.95 1761.83,3116.95 1785.45,3116.95 1809.07,3116.95 1832.7,3116.95 1856.32,3116.95 1879.94,3116.95 1903.56,3116.95 1927.18,3116.95 1950.81,3116.95 1976.43,3116.95 2000.05,3116.95 2023.67,3116.95 2047.29,3116.95 2070.92,3116.95 2091.31,3116.97 2113.48,3116.97 2130.87,3116.99 2153.03,3116.99 2175.2,3116.99 1108.99,3118.6 1127.89,3117.88 1151.52,3117.88 1175.14,3117.88 1198.76,3117.88 1222.38,3117.88 1246,3117.88 2213.63,3118.69 2239.25,3118.69 2262.87,3118.69 2286.49,3118.69 1460.52,3119.59 1484.14,3119.59 1504.25,3120.75 2197.36,3125.08 941.49,3128.45 904.55,3129.46 922.47,3129.25 1375.99,3129.54 1394.62,3129.54 1418.24,3129.54 1441.86,3129.54 1286.77,3130.72 2298.54,3130.64 998.27,3131.18 1021.89,3131.18 1045.51,3131.18 1069.13,3131.18 1092.76,3131.18 1357.36,3131.26 961.34,3132.18 979.25,3131.97 1313.14,3131.86 1332.95,3131.86 1265.02,3138.67 1108.99,3139.72 1127.89,3139 1151.52,3139 1175.14,3139 1198.76,3139 1222.38,3139 1246,3139 2219.38,3138.89 1525.61,3140.58 1549.23,3140.58 1572.85,3140.58 1596.48,3140.58 1620.1,3140.58 1643.72,3140.58 1667.34,3140.58 1690.96,3140.58 1714.59,3140.58 1738.21,3140.58 1761.83,3140.58 1785.45,3140.58 1809.07,3140.58 1832.7,3140.58 1856.32,3140.58 1879.94,3140.58 1903.56,3140.58 1927.18,3140.58 1950.81,3140.58 1976.43,3140.58 2000.05,3140.58 2023.67,3140.58 2047.29,3140.58 2070.92,3140.58 2091.31,3140.59 2113.48,3140.59 2135.64,3140.59 2157.81,3140.59 2179.97,3140.59 2239.25,3142.31 2262.87,3142.31 2286.49,3142.31 2310.12,3142.31 1460.52,3143.21 1484.14,3143.21 1504.25,3144.37 2199.92,3144.69 905.13,3146.59 922.47,3147.17 941.49,3149.58 961.91,3149.31 979.25,3149.89 998.86,3150.58 1045.51,3150.65 1068.79,3150.3 1092.6,3150.62 1286.97,3150.43 1312.9,3150.63 1333.29,3150.43 1357.46,3150.48 1375.99,3150.66 1394.62,3150.66 1418.24,3150.66 1441.86,3150.55 1021.89,3150.77
GPADC1: C3.2 R86.1 TP6.1 U1.M6 | length 309.6
  Top Layer w4: 1080.78,2425.97 1087.92,2418.83 U1.M6@1111,2418.83
  Top Layer w6: C3.2@921.49,2440.84 C3.2@922.09,2441.44 ; TP6.1@982.47,2485.72 938.84,2485.72 R86.1@938.39,2486.17 938.39,2457.74 C3.2@922.09,2441.44 ; 1080.78,2425.97 1059.75,2425.97 1026.52,2459.21 992.63,2459.21 974.86,2441.44 C3.2@922.09,2441.44
GPADC2: C78.2 R89.1 TP7.1 U1.L6 | length 2741.7
  Top Layer w6: U1.L6@1130.68,2418.83 1131.02,2418.49 1151.82,2418.49 v1(1152.16,2418.16)
  Top Layer w10: R89.1@2057.77,2302.21 2057.77,2281.49 v1(2070.3,2268.95) 2072.47,2268.95 2077.4,2273.88 TP7.1@2137.05,2273.88
  L3_SIG1 w6: v1(1152.16,2418.16) 1064.95,2418.16 1045.03,2438.07 997.67,2485.43 827.07,2485.43 779.2,2437.56 779.2,2264.96 901.81,2142.35 901.81,2054.14 1030.03,1925.91 1208.49,1925.91 1298.51,1835.89 v1(1498.87,1835.89)
  L3_SIG1 w10: v1@1520.57,2013.33 1520.57,1992.6 1549.87,1963.3 1578.95,1963.3 1647.7,2032.05 1707.96,2032.05 1962.82,2286.92 2022.94,2286.92 2040.9,2268.95 v1(2070.3,2268.95) 2164.71,2268.95 2178.94,2283.18 v1(2179.07,2283.18)
  Bottom Layer w6: v1(1498.87,1835.89) 1498.87,1855.27 1485.01,1869.13 1485.01,1895.06 1494.33,1904.37 1494.33,1966.18 1520.7,1992.55 v1(1520.7,2020.83)
  Bottom Layer w10: v1(2179.07,2283.18) 2181.24,2283.18 2185.51,2287.46 2199.42,2287.46 C78.2@2202.3,2290.33
HOST_CLK: TP4.1 U15.22 | length 66.1
  Top Layer w8: U15.22@1167,1780.76 1167,1732.94 1179.65,1720.28 TP4.1@1180.04,1720.28
I2C_SCL: J1.1 R25.2 R56.1 R60.1 R97.1 R108.2 R109.2 R137.2 R154.1 R159.2 R199.1 S5.2 U24.1 | length 9064.8
  Top Layer w6: v1(80.01,736.35) 80.01,732.16 87.04,725.13 R60.1@105.65,725.13 ; v1(267.96,2074.08) 267.96,2075.04 278.38,2085.47 285.83,2085.47 R109.2@289.94,2089.59 ; S5.2@657.84,99.25 658.23,99.64 v1(658.23,154.71) ; v1(1174.21,1199.92) 1205.73,1199.92 R199.1@1206.97,1198.69 ; v1(2108.35,1683.6) 2118.35,1683.6 2124.16,1689.41 2124.16,1715.18 R159.2@2124.33,1715.35
  L3_SIG1 w6: v1(80.01,736.35) 180.01,736.35 261.9,818.24 v1(261.9,1350.13) 286.08,1374.3 286.08,1547.84 465.71,1727.48 465.71,1775.98 543.98,1854.25 543.98,1944.79 413.72,2075.04 268.92,2075.04 v1(267.96,2074.08) 246.66,2095.38 246.66,2568.23 547.29,2868.86 547.29,3043.94 v1(572.49,3069.14) ; v1(1602.72,1511.89) 1617.12,1526.28 1750.43,1526.28 1762.52,1538.38 ; v1(1665.87,548.31) 1787.83,670.27 1787.83,1045.49 1836.35,1094.01 v1(1836.35,1116.8) 1836.35,1168.14 1809.77,1194.71 1780,1194.71 1762.5,1212.2 1762.5,1401.03 1756.19,1407.34 1756.19,1434.55 1762.52,1440.88 1762.52,1538.38 ; v1(1674.81,1949.78) 1762.52,1862.07 1762.52,1538.38
  L6_SIG2 w6: J1.1@166.94,1569.18 283.18,1569.18 318.89,1533.46 318.89,1407.12 v1(261.9,1350.13) ; v1(658.23,154.71) 705.67,202.15 865.67,202.15 888.02,224.5 955.69,224.5 1011.99,168.2 1369.83,168.2 1493.92,292.29 1493.92,471.59 1588.67,566.33 1647.85,566.33 v1(1665.87,548.31) ; v1(1174.21,1199.92) 1174.21,1220.72 1361.78,1408.29 1504.01,1408.29 v1@1600.43,1504.7 ; v1(1602.72,1511.89) 1632.3,1511.89 1718.15,1597.74 2022.49,1597.74 v1(2108.35,1683.6)
  Bottom Layer w6: R97.1@184.93,1368.14 186.91,1366.15 R154.1@227.56,1366.15 245.87,1366.15 v1(261.9,1350.13) 406.18,1350.13 504.01,1447.96 733.34,1447.96 811.68,1369.62 825.18,1369.62 825.28,1369.53 840.19,1369.53 840.28,1369.62 875.97,1369.62 893.48,1352.11 956.32,1352.11 1108.51,1199.92 v1(1174.21,1199.92) ; R137.2@532.63,3060.15 563.63,3060.15 572.49,3069.01 v1(572.49,3069.14) ; R108.2@1593.17,1481.18 1593.17,1502.33 v1(1602.72,1511.89) ; R56.1@1602.36,569.98 1644.2,569.98 v1(1665.87,548.31) ; R25.2@1648.77,1931.08 1667.47,1949.78 v1(1674.81,1949.78) ; U24.1@1807.7,1108.61 1824.91,1108.61 1833.1,1116.8 v1(1836.35,1116.8)
I2C_SDA: J1.2 R29.2 R55.1 R59.1 R98.1 R110.2 R111.2 R139.2 R160.2 R163.1 R197.1 S5.1 U24.4 | length 9906.2
  Top Layer w6: v1(77.45,763.99) R59.1@105.65,763.99 ; v1(211.39,2063.14) 211.62,2063.37 211.62,2098.69 217.1,2104.17 R111.2@228.87,2104.17 ; v1(605.61,156.52) 605.61,101.48 S5.1@607.84,99.25 ; v1(787.81,316.57) 695.51,408.87 695.51,564.65 743.7,612.83 1020.3,612.83 1080.6,673.14 v1(1080.6,689.54) ; v1(1162.29,1259.6) 1163.94,1257.95 R197.1@1206.97,1257.95 ; v1(2035.46,1731.81) 2035.46,1720.3 2043.76,1712 R160.2@2073.05,1712
  L3_SIG1 w6: v1(77.45,763.99) 146.98,763.99 221.78,838.79 v1(221.78,1317.9) 211.29,1328.39 211.29,1494.95 448.09,1731.75 448.09,1794.23 528.61,1874.75 528.61,1937.84 410.54,2055.91 220.42,2055.91 213.19,2063.14 v1(211.39,2063.14) 211.39,2232.03 230.94,2251.58 230.94,2795.89 v1(551.86,3116.81) ; v1(1541.26,1909.78) 1584.74,1909.78 1591.74,1902.78 1638.15,1902.78 ; v1(1783.19,1176.71) 1783.02,1176.71 1771.52,1165.2 1741.64,1165.2 1720.56,1186.29 1720.56,1427.84 1669.26,1479.13 1596.25,1479.13 1578.92,1496.47 v1(1578.92,1521.34) 1578.84,1521.41 1578.84,1533.81 1590.08,1545.05 1638.96,1545.05 1671.01,1577.1 1671.01,1869.93 1638.15,1902.78 ; v1(2035.46,1731.81) 1970.5,1666.84 1816.93,1666.84 1778.75,1705.02 1778.75,1890.78 1693.32,1976.21 1664.23,1976.21 1653.7,1965.68 1653.7,1918.33 1638.15,1902.78
  L6_SIG2 w6: J1.2@166.94,1669.18 311.31,1669.18 364.74,1615.75 364.74,1388.87 293.77,1317.9 v1(221.78,1317.9) ; v1(605.61,156.52) 765.66,316.57 v1(787.81,316.57) ; v1(1080.6,689.54) 1056.51,689.54 1041,705.04 1041,770.81 1155.18,884.99 1155.18,1113.34 1136.48,1132.04 1136.48,1233.78 v1(1162.29,1259.6) 1391.88,1489.18 1546.76,1489.18 v1(1578.92,1521.34)
  Bottom Layer w6: R98.1@184.5,1294.02 185.3,1294.83 R163.1@221.78,1294.83 v1(221.78,1317.9) 221.78,1333.18 212.79,1342.17 169.2,1342.17 117.9,1393.46 117.9,1417.8 128.69,1428.58 419.23,1428.58 452.21,1461.56 738.32,1461.56 788.69,1411.19 970.63,1411.19 1122.22,1259.6 v1(1162.29,1259.6) ; R139.2@516.59,3127.45 541.21,3127.45 v1(551.86,3116.81) ; v1(1080.6,689.54) 1103.87,666.26 1179.68,666.26 1204.97,640.97 1422.61,640.97 R55.1@1455.18,608.39 ; v1(1541.26,1909.78) 1550.23,1900.81 1605.13,1900.81 1664.54,1841.39 1691.32,1841.39 R29.2@1691.51,1841.58 ; v1(1578.92,1521.34) 1600.41,1542.83 R110.2@1636.03,1542.83 ; v1(1783.19,1176.71) 1783.19,1162.51 1789.85,1155.85 U24.4@1805.73,1155.85
LIN_BUS: C132.1 J4.3 R21.1 U23.6 | length 689.9
  Top Layer w6: J4.3@67.09,2808.93 169.08,2808.93 209.94,2849.8 390.41,2849.8 407.46,2832.74 C132.1@407.46,2779.11 406.02,2777.67 379.77,2777.67 371.77,2769.67 371.77,2711.41 380.98,2702.2 432.42,2702.2 442.07,2692.55 R21.1@442.07,2596.59
LIN_PHY_EN: R17.1 R88.2 U23.2 | length 112.3
  Top Layer w6: U23.2@506.67,2676.61 567.87,2676.61 R17.1@570.24,2674.25 570.24,2721.82 R88.2@570.13,2721.93
LIN_PHY_EN_CTRL: R88.1 S4.3 | length 2802.1
  Top Layer w6: R88.1@617.38,2721.93 683.89,2721.93 713.62,2692.19 v1(713.62,2670.02) ; v1(1913.68,2090.16) 1987.87,2090.16 2027.06,2050.96 2027.06,2006.23 2081.36,1951.93 2310.71,1951.93 2350.12,1912.53 2350.12,1708.93 2321.07,1679.89 2274.99,1679.89 2235.09,1639.98 2129.19,1639.98 2117.31,1628.1 2117.31,1592.91 S4.3@2117.14,1592.74
  L6_SIG2 w6: v1(713.62,2670.02) 824.17,2670.02 1121.96,2372.23 1121.96,2334.25 1145.04,2311.17 1183.19,2311.17 1270.05,2224.31 1270.05,2173.12 1305.63,2137.54 1344.13,2137.54 1359.62,2153.02 1447.72,2153.02 1510.73,2216.03 1603.83,2216.03 1620.76,2232.96 1620.76,2267.1 1632.89,2279.24 1724.6,2279.24 v1(1913.68,2090.16)
LIN_PHY_RX: R18.1 R22.1 U15.2 | length 2331.7
  Top Layer w6: R22.1@609.31,2605.16 R18.1@565.2,2605.17 565.2,2550.09 487.18,2472.07 487.18,2278.59 463.94,2255.34 355.53,2255.34 346.24,2264.62 346.24,2325.93 325.1,2347.07 172.03,2347.07 122.34,2297.37 122.34,2108.57 198.35,2032.55 233.8,2032.55 256.73,2055.47 499.96,2055.47 552.78,2002.66 741.23,2002.66 764.73,2026.16 877.36,2026.16 918.83,1984.69 918.83,1945.81 942.31,1922.33 1150.83,1922.33 1192.59,1964.09 U15.2@1192.59,2009.1
LIN_VDD: C123.1 D8.2 R31.2 R32.2 U23.7 | length 260.1
  Top Layer w14: C123.1@338.92,2651.2 364.34,2676.61 U23.7@404.31,2676.61
  Top Layer w30: R31.2@338.92,2698.44 C123.1@338.92,2651.2 339.67,2650.45 339.67,2603.59 352.23,2591.03 353.73,2591.03 ; R31.2@339.35,2714.2 R32.2@339.35,2783.93
LVDS_CLK_RTC_CLKIN_TP: U1.L11 U15.10 | length 541.4
  Top Layer w4: v1@1149.51,2339.23 v1@1149.84,2339.23
  Top Layer w6: U15.10@987.86,2009.1 987.86,2060.95 v1(991.85,2064.93) ; U1.L11@1130.68,2320.4 v1@1149.51,2339.23
  L3_SIG1 w6: v1(991.85,2064.93) 972.16,2064.93 929.38,2107.72 929.38,2212.08 967.1,2249.8 1021,2249.8 1045.03,2273.83 1109.72,2338.52 v1@1149.38,2338.52
  other v1: 1149.38,2339.52
LVDS_D0_LIN_PHY_RX: U1.H10 U15.4 | length 540
  Top Layer w6: v1(1131.47,1943.91) 1131.35,1944.04 1131.35,1955.17 1141.41,1965.24 U15.4@1141.41,2009.1 ; U1.H10@1189.74,2340.09 v1(1206.92,2340.1)
  L3_SIG1 w6: v1(1131.47,1943.91) 1131.47,1962.41 1100.71,1993.17 1100.71,2012.81 1129.54,2041.65 1129.54,2193.33 1162.08,2225.87 1162.08,2296.11 1206.07,2340.1 v1(1206.92,2340.1)
LVDS_D1_XDS_UARTA_RX_CAN_RX: U1.J11 U15.6 | length 567.7
  Top Layer w4: 1167.39,2194.59 1167.39,2238.86 1170.46,2241.93 1170.46,2319.99 U1.J11@1170.05,2320.4
  Top Layer w6: U15.6@1090.23,2009.1 1091.98,2010.86 1091.98,2049.41 1097.17,2054.59 1121.6,2054.59 1128.26,2061.25 1128.26,2071.32 1123.4,2076.19 1094.56,2076.19 1089.86,2080.88 1089.86,2090.52 1095.14,2095.79 1127,2095.79 1132.19,2100.97 1132.19,2113.28 1128.48,2116.99 1057.09,2116.99 1052.16,2121.92 1052.16,2136.1 1061.14,2145.08 1117.89,2145.08 1167.39,2194.58
LVDS_D2_XDS_UARTA_TX_CAN_TX: U1.L12 U15.7 | length 564.8
  Top Layer w6: U15.7@1064.64,2009.1 1064.64,2071.69 1053.94,2082.39 1004.57,2082.39 993.81,2093.15 993.81,2104.9 1005.59,2116.67 1029.14,2116.67 1035.18,2122.71 1035.18,2137.24 1029.11,2143.31 999.17,2143.31 990.18,2152.3 990.18,2169.91 999.24,2178.97 1032.54,2178.97 1037.49,2183.92 1037.49,2193.6 1043.59,2199.7 1054.96,2199.7 1061.36,2193.3 1061.36,2177.13 1067.12,2171.37 1078.69,2171.37 1092.92,2185.6 1092.92,2256.85 1124.59,2288.52 1124.59,2294.63 U1.L12@1130.68,2300.72
LVDS_D3_nERROR_LED_WD_TP: U1.K11 U15.9 | length 539.9
  Top Layer w4: U1.K11@1150.37,2320.4 1161.73,2308.54 1161.73,2273.4 1156.27,2267.44 1156.27,2199.02
  Top Layer w6: U15.9@1013.46,2009.1 1013.46,2051.84 v1(1018.71,2057.09) ; v1(1109.31,2173.72) 1130.97,2173.72 1156.27,2199.02
  L3_SIG1 w6: v1(1018.71,2057.09) 1081.02,2057.09 1090.36,2066.43 1090.36,2087.94 1081.23,2097.08 1033.69,2097.08 1025.71,2105.06 1025.71,2125.1 1034.97,2134.36 1065.21,2134.36 1074.55,2143.7 1074.55,2162.99 1085.28,2173.72 v1(1109.31,2173.72) v1@1109.59,2173.44
LVDS_FRCLK_HOST_CLK_TP: U1.M10 U15.12 | length 565
  Top Layer w6: U15.12@936.68,2009.1 936.68,2059.15 944.31,2066.77 963.81,2066.77 971.86,2074.82 971.86,2088.38 964.66,2095.58 945.59,2095.58 939.24,2101.94 939.24,2114.65 945.17,2120.58 963.39,2120.58 971.7,2128.9 971.7,2144.22 965.19,2150.73 946.4,2150.73 941.33,2155.8 941.33,2281.98 991.75,2332.4 1101.59,2332.4 1109.27,2340.09 U1.M10@1111,2340.09
MCU_3V3: C76.1 J8.1 R132.1
MCU_5V: C77.1 J8.2 R87.1
MCU_SOP0: R13.1 R164.1 | length 2427.5
  Top Layer w6: R13.1@763.22,459.76 763.22,437.42 v1(771.01,429.63)
  L3_SIG1 w6: v1(771.01,429.63) 734.2,392.82 734.2,170.71 805.07,99.85 1186.19,99.85 1445.19,358.84 1575.74,358.84 1979.19,762.29 1979.19,986.63 1901.55,1064.28 1901.55,1250.8 1917.3,1266.55 v1(1917.5,1266.55)
  Bottom Layer w6: R164.1@1911.01,1291.98 1911.01,1273.03 v1(1917.5,1266.55)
